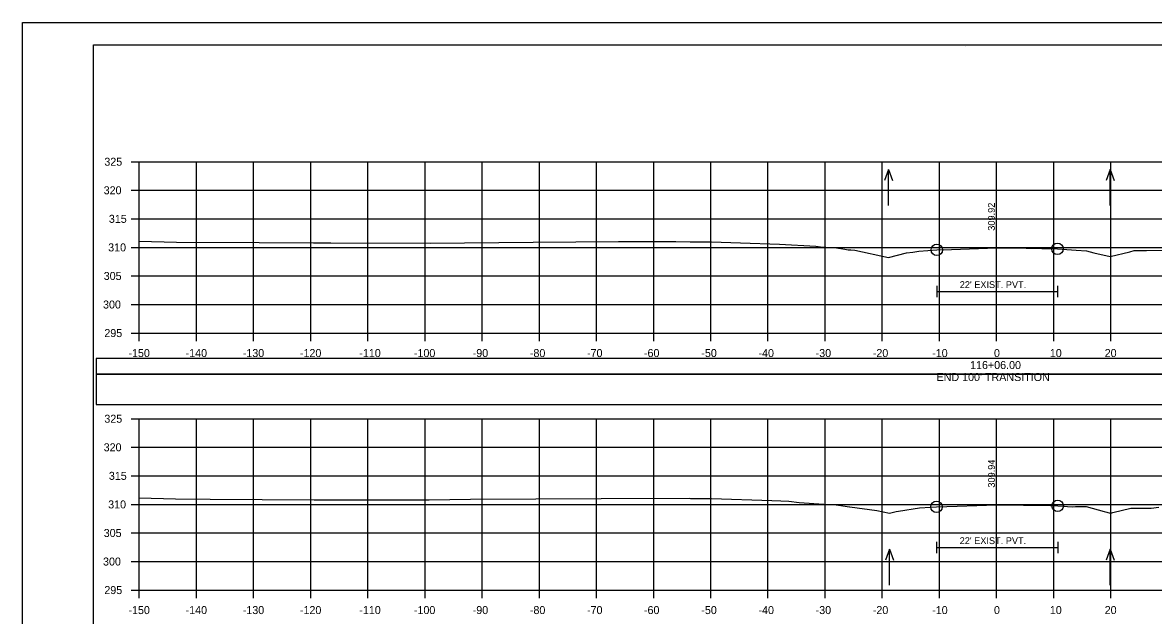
# Model space of a CAD drawing. Extents: x 1370538 to 1372872, y 376220 to 381127.
# Drawn here: x 1371204.9 to 1371402.7, y 380794.6 to 380898.4 of the extents above; entities that cross this region are included whole.
import ezdxf

# ---------------------------------------------------------------- set-up
doc = ezdxf.new("R2010")
doc.units = 0
for name, color, linetype in [('R_Border', 7, 'Continuous'), ('R_Border Notes', 7, 'Continuous'), ('R_Border PE', 7, 'Continuous'), ('R_Border Prem', 7, 'Continuous'), ('R_Dimension', 7, 'Continuous'), ('R_Grid', 7, 'Continuous'), ('R_No Plot', 7, 'Continuous'), ('R_Water', 7, 'Continuous'), ('R_Water Annot', 7, 'Continuous'), ('R_Xsect Elev', 7, 'Continuous'), ('T_Detection Zones', 7, 'Continuous')]:
    doc.layers.add(name, color=color, linetype=linetype)

msp = doc.modelspace()

# ---------------------------------------------------------------- linework, layer by layer
at = {"layer": 'R_Border'}
for p, q in [((1371364.83, 380852.32), (1371364.83, 380850.32)), ((1371364.83, 380851.32), (1371385.95, 380851.32)), ((1371385.95, 380852.32), (1371385.95, 380850.32)), ((1371364.78, 380807.49), (1371364.78, 380805.49)), ((1371385.98, 380807.49), (1371385.98, 380805.49)), ((1371364.78, 380806.49), (1371385.98, 380806.49))]:
    msp.add_line(p, q, dxfattribs=at)
at = {"layer": 'R_Border Notes'}
for p, q in [((1371217.29, 380894.5), (1371533.47, 380894.5)), ((1371217.29, 380689.04), (1371217.29, 380894.5)), ((1371369.81, 380894.24), (1371369.81, 380894.24)), ((1371369.81, 380894.24), (1371369.81, 380894.24))]:
    msp.add_line(p, q, dxfattribs=at)
at = {"layer": 'R_Border Prem'}
for p, q in [((1371223.89, 380874.04), (1371225.29, 380874.04)), ((1371225.29, 380844.04), (1371225.29, 380874.04)), ((1371223.89, 380869.04), (1371225.29, 380869.04)), ((1371223.89, 380864.04), (1371225.29, 380864.04)), ((1371223.89, 380859.04), (1371225.29, 380859.04)), ((1371223.89, 380854.04), (1371225.29, 380854.04)), ((1371223.89, 380849.04), (1371225.29, 380849.04)), ((1371223.89, 380844.04), (1371225.29, 380844.04)), ((1371225.29, 380844.04), (1371525.29, 380844.04)), ((1371225.29, 380842.64), (1371225.29, 380844.04)), ((1371235.29, 380842.64), (1371235.29, 380844.04)), ((1371245.29, 380842.64), (1371245.29, 380844.04)), ((1371255.29, 380842.64), (1371255.29, 380844.04)), ((1371265.29, 380842.64), (1371265.29, 380844.04)), ((1371275.29, 380842.64), (1371275.29, 380844.04)), ((1371285.29, 380842.64), (1371285.29, 380844.04)), ((1371295.29, 380842.64), (1371295.29, 380844.04)), ((1371305.29, 380842.64), (1371305.29, 380844.04)), ((1371315.29, 380842.64), (1371315.29, 380844.04)), ((1371325.29, 380842.64), (1371325.29, 380844.04)), ((1371335.29, 380842.64), (1371335.29, 380844.04)), ((1371345.29, 380842.64), (1371345.29, 380844.04)), ((1371355.29, 380842.64), (1371355.29, 380844.04)), ((1371365.29, 380842.64), (1371365.29, 380844.04)), ((1371375.29, 380842.64), (1371375.29, 380844.04)), ((1371385.29, 380842.64), (1371385.29, 380844.04)), ((1371395.29, 380842.64), (1371395.29, 380844.04)), ((1371223.89, 380829.04), (1371225.29, 380829.04)), ((1371225.29, 380799.04), (1371225.29, 380829.04)), ((1371223.89, 380824.04), (1371225.29, 380824.04)), ((1371223.89, 380819.04), (1371225.29, 380819.04)), ((1371223.89, 380814.04), (1371225.29, 380814.04)), ((1371223.89, 380809.04), (1371225.29, 380809.04)), ((1371223.89, 380804.04), (1371225.29, 380804.04)), ((1371223.89, 380799.04), (1371225.29, 380799.04)), ((1371225.29, 380799.04), (1371525.29, 380799.04)), ((1371225.29, 380797.64), (1371225.29, 380799.04)), ((1371235.29, 380797.64), (1371235.29, 380799.04)), ((1371245.29, 380797.64), (1371245.29, 380799.04)), ((1371255.29, 380797.64), (1371255.29, 380799.04)), ((1371265.29, 380797.64), (1371265.29, 380799.04)), ((1371275.29, 380797.64), (1371275.29, 380799.04)), ((1371285.29, 380797.64), (1371285.29, 380799.04)), ((1371295.29, 380797.64), (1371295.29, 380799.04)), ((1371305.29, 380797.64), (1371305.29, 380799.04)), ((1371315.29, 380797.64), (1371315.29, 380799.04)), ((1371325.29, 380797.64), (1371325.29, 380799.04)), ((1371335.29, 380797.64), (1371335.29, 380799.04)), ((1371345.29, 380797.64), (1371345.29, 380799.04)), ((1371355.29, 380797.64), (1371355.29, 380799.04)), ((1371365.29, 380797.64), (1371365.29, 380799.04)), ((1371375.29, 380797.64), (1371375.29, 380799.04)), ((1371385.29, 380797.64), (1371385.29, 380799.04)), ((1371395.29, 380797.64), (1371395.29, 380799.04))]:
    msp.add_line(p, q, dxfattribs=at)
at = {"layer": 'R_Dimension'}
for points in [[(1371225.29, 380860.13), (1371231.81, 380859.97), (1371246.28, 380859.88), (1371255.8, 380859.82), (1371258.79, 380859.83), (1371276.16, 380859.79), (1371294.19, 380859.97), (1371309.12, 380860.07), (1371319.16, 380860.09), (1371321.65, 380860.02), (1371323.77, 380860.02), (1371325.43, 380860.01), (1371330.47, 380859.84), (1371337.29, 380859.63), (1371343.67, 380859.23), (1371344.46, 380859.13), (1371346.33, 380859), (1371347.26, 380858.95), (1371348.74, 380858.72), (1371349.32, 380858.64), (1371349.76, 380858.64), (1371350.46, 380858.55), (1371356.37, 380857.3), (1371359.54, 380858.08), (1371360.65, 380858.22), (1371361.69, 380858.39), (1371363.25, 380858.49), (1371364.83, 380858.6), (1371367.37, 380858.69), (1371375.27, 380858.96), (1371380.46, 380858.88), (1371385.95, 380858.78), (1371389.22, 380858.57), (1371390.99, 380858.46), (1371392.29, 380858.11), (1371395.13, 380857.45), (1371398.61, 380858.27), (1371399.37, 380858.49), (1371401.53, 380858.5), (1371411.24, 380858.63)], [(1371225.29, 380815.2), (1371231.6, 380815.04), (1371237.71, 380814.95), (1371255.87, 380814.85), (1371269.08, 380814.87), (1371276.02, 380814.86), (1371283.24, 380814.93), (1371306.1, 380815.09), (1371321.48, 380815.11), (1371321.74, 380815.1), (1371321.96, 380815.1), (1371325.43, 380815.09), (1371335.97, 380814.74), (1371337.51, 380814.69), (1371338.95, 380814.6), (1371340.75, 380814.37), (1371345.08, 380814.07), (1371347.21, 380813.95), (1371347.62, 380813.89), (1371349.56, 380813.64), (1371349.63, 380813.64), (1371354.33, 380812.98), (1371356.54, 380812.51), (1371357.72, 380812.8), (1371358.14, 380812.86), (1371361.77, 380813.42), (1371363.74, 380813.56), (1371364.78, 380813.61), (1371368.36, 380813.74), (1371375.28, 380813.98), (1371384.74, 380813.83), (1371385.98, 380813.8), (1371388.57, 380813.64), (1371389.12, 380813.7), (1371389.85, 380813.67), (1371390.96, 380813.65), (1371394.08, 380812.8), (1371394.55, 380812.67), (1371395.17, 380812.52), (1371395.46, 380812.59), (1371395.61, 380812.6), (1371398.78, 380813.38), (1371402.33, 380813.37), (1371403.69, 380813.56)]]:
    msp.add_lwpolyline(points, dxfattribs=at)
at = {"layer": 'R_Grid'}
for p, q in [((1371225.29, 380874.04), (1371525.29, 380874.04)), ((1371225.29, 380844.04), (1371225.29, 380874.04)), ((1371235.29, 380844.04), (1371235.29, 380874.04)), ((1371245.29, 380844.04), (1371245.29, 380874.04)), ((1371255.29, 380844.04), (1371255.29, 380874.04)), ((1371265.29, 380844.04), (1371265.29, 380874.04)), ((1371275.29, 380844.04), (1371275.29, 380874.04)), ((1371285.29, 380844.04), (1371285.29, 380874.04)), ((1371295.29, 380844.04), (1371295.29, 380874.04)), ((1371305.29, 380844.04), (1371305.29, 380874.04)), ((1371315.29, 380844.04), (1371315.29, 380874.04)), ((1371325.29, 380844.04), (1371325.29, 380874.04)), ((1371335.29, 380844.04), (1371335.29, 380874.04)), ((1371345.29, 380844.04), (1371345.29, 380874.04)), ((1371355.29, 380844.04), (1371355.29, 380874.04)), ((1371365.29, 380844.04), (1371365.29, 380874.04)), ((1371375.29, 380844.04), (1371375.29, 380874.04)), ((1371385.29, 380844.04), (1371385.29, 380874.04)), ((1371395.29, 380844.04), (1371395.29, 380874.04)), ((1371225.29, 380869.04), (1371525.29, 380869.04)), ((1371225.29, 380864.04), (1371525.29, 380864.04)), ((1371225.29, 380859.04), (1371525.29, 380859.04)), ((1371225.29, 380854.04), (1371525.29, 380854.04)), ((1371225.29, 380849.04), (1371525.29, 380849.04)), ((1371225.29, 380844.04), (1371525.29, 380844.04)), ((1371225.29, 380829.04), (1371525.29, 380829.04)), ((1371225.29, 380799.04), (1371225.29, 380829.04)), ((1371235.29, 380799.04), (1371235.29, 380829.04)), ((1371245.29, 380799.04), (1371245.29, 380829.04)), ((1371255.29, 380799.04), (1371255.29, 380829.04)), ((1371265.29, 380799.04), (1371265.29, 380829.04)), ((1371275.29, 380799.04), (1371275.29, 380829.04)), ((1371285.29, 380799.04), (1371285.29, 380829.04)), ((1371295.29, 380799.04), (1371295.29, 380829.04)), ((1371305.29, 380799.04), (1371305.29, 380829.04)), ((1371315.29, 380799.04), (1371315.29, 380829.04)), ((1371325.29, 380799.04), (1371325.29, 380829.04)), ((1371335.29, 380799.04), (1371335.29, 380829.04)), ((1371345.29, 380799.04), (1371345.29, 380829.04)), ((1371355.29, 380799.04), (1371355.29, 380829.04)), ((1371365.29, 380799.04), (1371365.29, 380829.04)), ((1371375.29, 380799.04), (1371375.29, 380829.04)), ((1371385.29, 380799.04), (1371385.29, 380829.04)), ((1371395.29, 380799.04), (1371395.29, 380829.04)), ((1371225.29, 380824.04), (1371525.29, 380824.04)), ((1371225.29, 380819.04), (1371525.29, 380819.04)), ((1371225.29, 380814.04), (1371525.29, 380814.04)), ((1371225.29, 380809.04), (1371525.29, 380809.04)), ((1371225.29, 380804.04), (1371525.29, 380804.04)), ((1371225.29, 380799.04), (1371525.29, 380799.04))]:
    msp.add_line(p, q, dxfattribs=at)
at = {"layer": 'R_No Plot'}
msp.add_line((1371204.89, 380898.4), (1371538.22, 380898.4), dxfattribs=at)
for points in [[(1371204.88, 380898.4), (1371538.22, 380898.4), (1371538.22, 380685.06), (1371204.88, 380685.06)], [(1371451.21, 380894.5), (1371451.21, 380884.62), (1371486.94, 380884.62), (1371486.94, 380881.7), (1371510.14, 380881.7), (1371510.14, 380857.37), (1371533.47, 380857.37), (1371533.47, 380689.04), (1371217.29, 380689.04), (1371217.29, 380894.5)]]:
    msp.add_lwpolyline(points, close=True, dxfattribs=at)
for centre in [(1371364.83, 380858.6), (1371385.95, 380858.78), (1371364.78, 380813.61), (1371385.98, 380813.8)]:
    msp.add_circle(centre, 1, dxfattribs=at)
at = {"layer": 'R_Water Annot'}
for p, q in [((1371356.37, 380872.67), (1371355.67, 380870.75)), ((1371356.37, 380866.39), (1371356.37, 380872.67)), ((1371356.37, 380872.67), (1371357.07, 380870.75)), ((1371395.13, 380872.67), (1371394.43, 380870.75)), ((1371395.13, 380866.39), (1371395.13, 380872.67)), ((1371395.13, 380872.67), (1371395.83, 380870.75)), ((1371356.54, 380806.18), (1371355.84, 380804.25)), ((1371356.54, 380799.89), (1371356.54, 380806.18)), ((1371356.54, 380806.18), (1371357.24, 380804.25)), ((1371395.17, 380806.18), (1371394.47, 380804.25)), ((1371395.17, 380799.89), (1371395.17, 380806.18)), ((1371395.17, 380806.18), (1371395.87, 380804.25))]:
    msp.add_line(p, q, dxfattribs=at)
at = {"layer": 'R_Xsect Elev'}
for p, q in [((1371375.29, 380858.96), (1371375.29, 380868.96)), ((1371375.29, 380813.98), (1371375.29, 380823.98))]:
    msp.add_line(p, q, dxfattribs=at)
at = {"layer": 'T_Detection Zones'}
for points in [[(1371217.73, 380836.87), (1371532.86, 380836.87), (1371532.86, 380839.58), (1371217.73, 380839.58)], [(1371217.73, 380831.55), (1371532.86, 380831.55), (1371532.86, 380836.87), (1371217.73, 380836.87)]]:
    msp.add_lwpolyline(points, close=True, dxfattribs=at)

# ---------------------------------------------------------------- texts
at = {"layer": 'R_Border PE'}
for s, p in [('325', (1371219.18, 380873.34)), ('320', (1371219.06, 380868.34)), ('315', (1371219.97, 380863.34)), ('310', (1371219.85, 380858.34)), ('305', (1371219.07, 380853.34)), ('300', (1371218.95, 380848.34)), ('295', (1371219.18, 380843.34)), ('-150', (1371223.4, 380839.84)), ('-140', (1371233.4, 380839.84)), ('-130', (1371243.4, 380839.84)), ('-120', (1371253.4, 380839.84)), ('-110', (1371263.79, 380839.84)), ('-100', (1371273.34, 380839.84)), ('-90', (1371283.63, 380839.84)), ('-80', (1371293.63, 380839.84)), ('-70', (1371303.63, 380839.84)), ('-60', (1371313.59, 380839.84)), ('-50', (1371323.63, 380839.84)), ('-40', (1371333.63, 380839.84)), ('-30', (1371343.63, 380839.84)), ('-20', (1371353.63, 380839.84)), ('-10', (1371364.02, 380839.84)), ('0', (1371374.83, 380839.84)), ('10', (1371384.6, 380839.84)), ('20', (1371394.2, 380839.84)), ('116+06.00', (1371370.65, 380837.74)), ("END 100' TRANSITION", (1371364.78, 380835.64)), ('325', (1371219.18, 380828.34)), ('320', (1371219.06, 380823.34)), ('315', (1371219.97, 380818.34)), ('310', (1371219.85, 380813.34)), ('305', (1371219.07, 380808.34)), ('300', (1371218.95, 380803.34)), ('295', (1371219.18, 380798.34)), ('-150', (1371223.4, 380794.84)), ('-140', (1371233.4, 380794.84)), ('-130', (1371243.4, 380794.84)), ('-120', (1371253.4, 380794.84)), ('-110', (1371263.79, 380794.84)), ('-100', (1371273.34, 380794.84)), ('-90', (1371283.63, 380794.84)), ('-80', (1371293.63, 380794.84)), ('-70', (1371303.63, 380794.84)), ('-60', (1371313.59, 380794.84)), ('-50', (1371323.63, 380794.84)), ('-40', (1371333.63, 380794.84)), ('-30', (1371343.63, 380794.84)), ('-20', (1371353.63, 380794.84)), ('-10', (1371364.02, 380794.84)), ('0', (1371374.83, 380794.84)), ('10', (1371384.6, 380794.84)), ('20', (1371394.2, 380794.84))]:
    msp.add_text(s, height=1.4, dxfattribs=at).set_placement(p)
at = {"layer": 'R_Water'}
for p in [(1371368.84, 380851.92), (1371368.83, 380807.09)]:
    msp.add_text("22' EXIST. PVT.", height=1.2, dxfattribs=at).set_placement(p)
at = {"layer": 'R_Xsect Elev'}
for s, p in [('309.92', (1371374.99, 380861.96)), ('309.94', (1371374.99, 380816.98))]:
    msp.add_text(s, height=1.2, rotation=90, dxfattribs=at).set_placement(p)

doc.saveas('drawing.dxf')
